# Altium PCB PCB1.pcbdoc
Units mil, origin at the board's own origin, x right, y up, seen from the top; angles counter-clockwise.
Board outline 4456.4 x 1879 mil, 2 copper layers (Top Layer, Bottom Layer), stack 62.2 mil thick; 77 components, 60 nets, 283 pads, 100 vias.
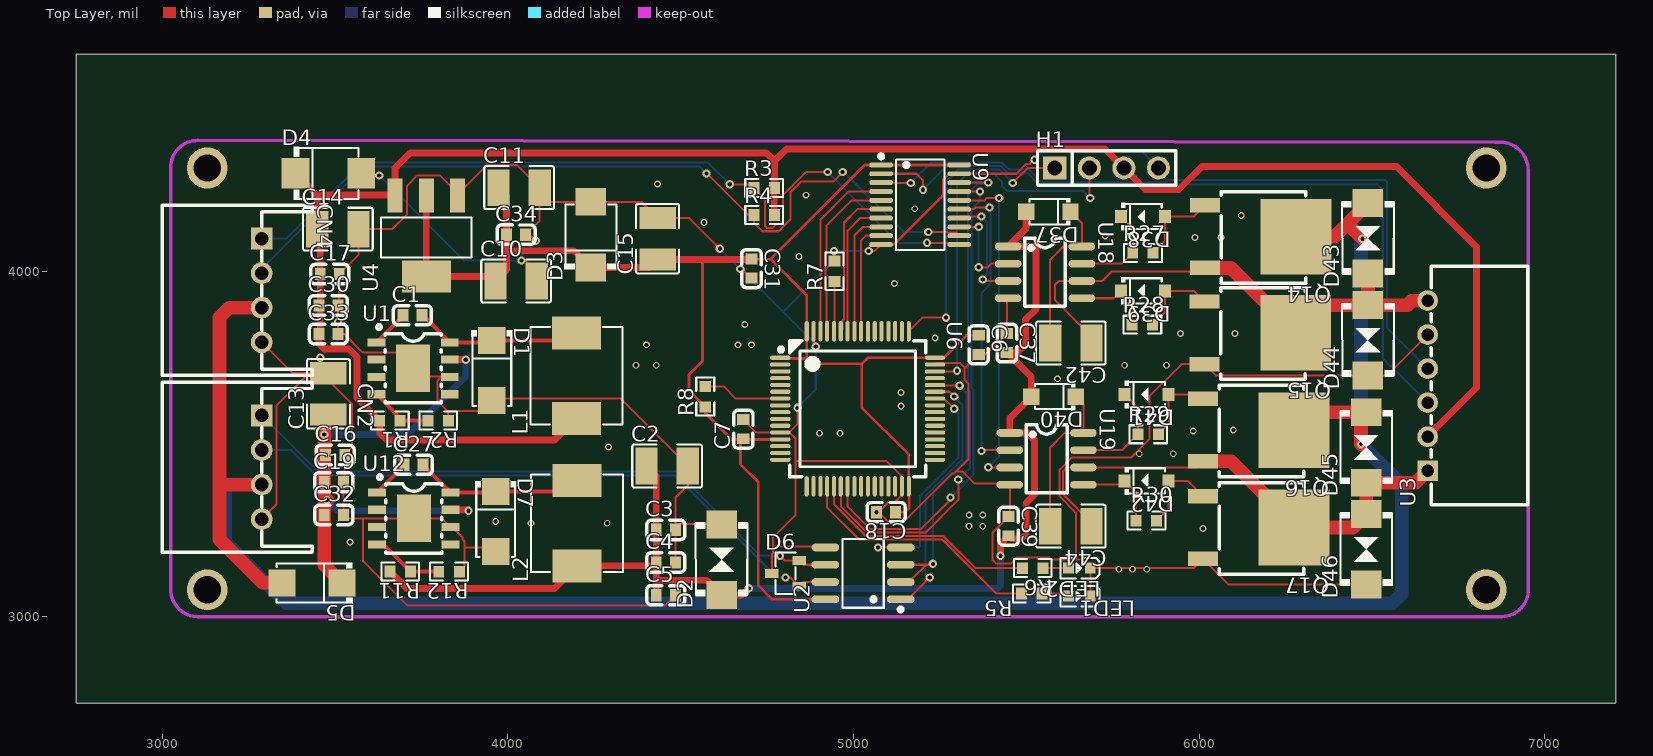
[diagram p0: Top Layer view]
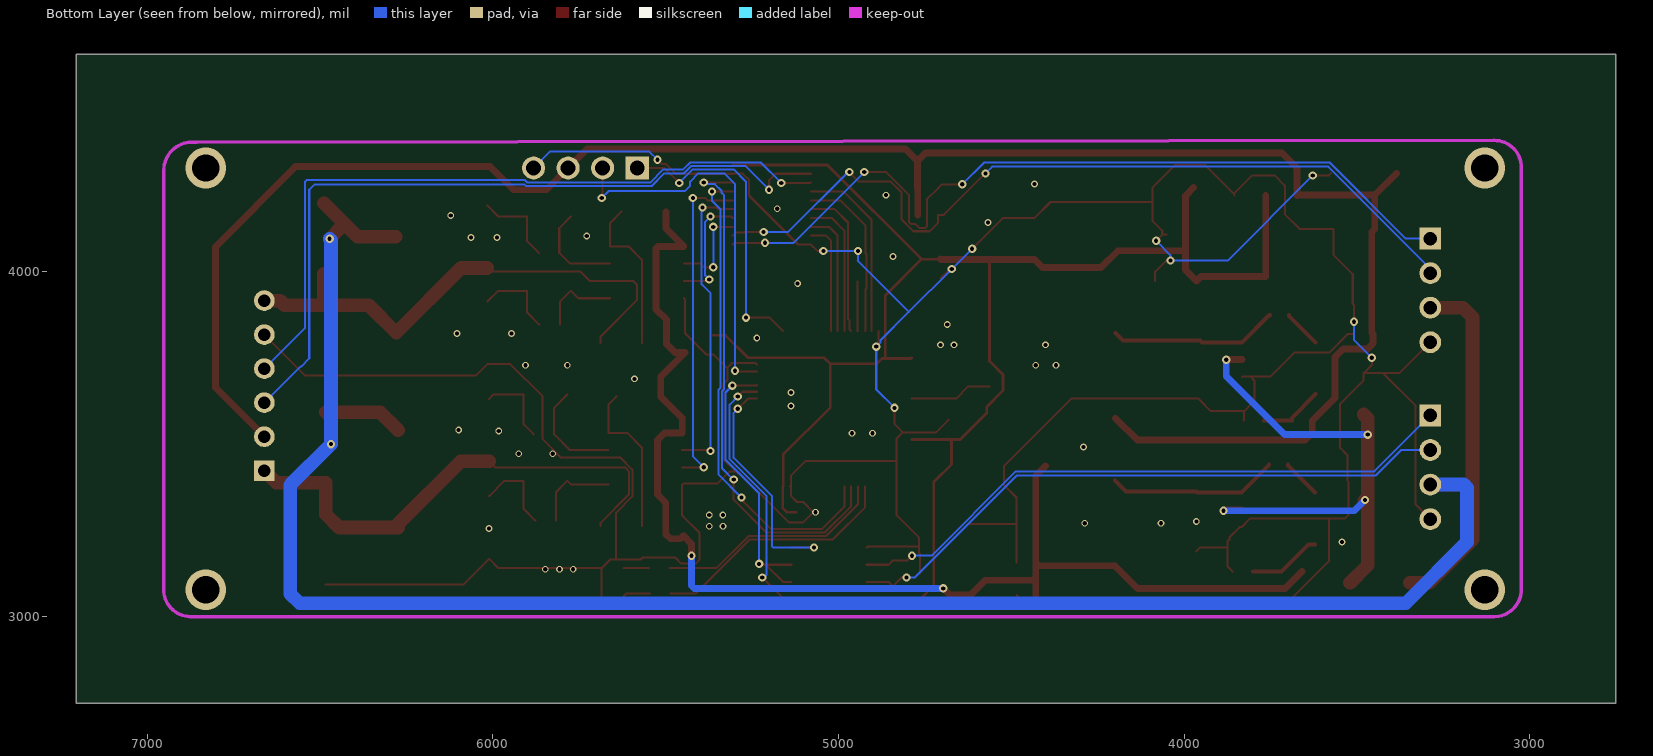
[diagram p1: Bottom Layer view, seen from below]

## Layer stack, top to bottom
Top Solder Mask Layer: solder mask 0.4, Dk 3.3
Top Layer: signal copper 1.4
Dielectric1: surface 59.4, FR4, Dk 4.5
Bottom Layer: signal copper 1.4
Bottom Solder Mask Layer: solder mask 0.4, Dk 3.3

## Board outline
7206.4,2750 2750,2750 2750,4629 7206.4,4629

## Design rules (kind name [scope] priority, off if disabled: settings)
BoardOutlineClearance copperThickness1oz [All] p0: genericclearance=10 ignorepadtopadclearanceinfootprint=FALSE except(0: Arc-SplitContinuation Track-SplitContinuation SMDPad-SplitContinuation THPad-SplitContinuation Via-SplitContinuation Fill-SplitContinuation Poly-SplitContinuation Region-SplitContinuation Text-SplitContinuation)
BoardOutlineClearance copperThickness2oz [All] p0: genericclearance=10 ignorepadtopadclearanceinfootprint=FALSE except(0: Arc-SplitContinuation Track-SplitContinuation SMDPad-SplitContinuation THPad-SplitContinuation Via-SplitContinuation Fill-SplitContinuation Poly-SplitContinuation Region-SplitContinuation Text-SplitContinuation)
BoardOutlineClearance otherClearance [All] p0: genericclearance=10 ignorepadtopadclearanceinfootprint=FALSE except(0: Arc-SplitContinuation Track-SplitContinuation SMDPad-SplitContinuation THPad-SplitContinuation Via-SplitContinuation Fill-SplitContinuation Poly-SplitContinuation Region-SplitContinuation Text-SplitContinuation)
Clearance copperThickness1oz [All] p1: gap=7 ignorepadtopadclearanceinfootprint=FALSE
Clearance copperThickness2oz [All] p1: gap=7 ignorepadtopadclearanceinfootprint=FALSE
Clearance otherClearance [All] p1: gap=7 ignorepadtopadclearanceinfootprint=FALSE
DiffPairsRouting differentialPair [All] p1: maxuncoupledlength=10 minlimit=6 maxlimit=Infinity mostfreqgap=6 toplayer_minwidth=5 toplayer_prefwidth=10 toplayer_maxwidth=100 bottomlayer_minwidth=5 bottomlayer_prefwidth=10 bottomlayer_maxwidth=100
PasteMaskExpansion pasteMaskExpansion [All] p1: expansion=0
PlaneConnect innerPlane [All] p1: planeconnectstyle=Direct reliefexpansion=20 reliefentries=4 reliefconductorwidth=10 reliefairgap=10
PolygonConnect copperRegion [All] p1: connectstyle=Direct reliefentries=4 reliefconductorwidth=10 polygonreliefangle="90 Angle" airgapwidth=10
RoutingVias viaSize [All] p1: viastyle="Through Hole" holewidth=12.0078 minholewidth=11.811 maxholewidth=248.0314 width=12.0078 minwidth=11.811 maxwidth=248.0314
SolderMaskExpansion solderMaskExpansion [IsVia] p1: useseparateexpansions=TRUE expansion=-1000 expansionbottom=-1000
SolderMaskExpansion solderMaskExpansion [All] p2: useseparateexpansions=TRUE expansion=2 expansionbottom=2
Width copperThickness1oz [All] p1: maxlimit=100 minlimit=5 preferedwidth=6
Width copperThickness2oz [All] p1: maxlimit=100 minlimit=8 preferedwidth=10
Width l24V [All] p1: maxlimit=100 minlimit=4 preferedwidth=39
Width i5V [All] p1: maxlimit=100 minlimit=5 preferedwidth=20
Width i3V [All] p1: maxlimit=100 minlimit=5 preferedwidth=8

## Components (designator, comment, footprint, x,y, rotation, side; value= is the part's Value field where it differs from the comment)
C1 "100nF" C0603#1 3723.3,3873 r0 top
C2 "10uF" C1210#1 4460.6,3437 r0 top
C3 "100nF" C0603#2 4456.7,3252 r0 top
C4 "100nF" C0603#2 4456.7,3157.5 r0 top
C5 "100nF" C0603#2 4456.7,3063 r0 top
C6 "100nF" C0603#2 5362.2,3787.4 r270 top
C7 "100nF" C0603#2 4681.1,3543.3 r90 top
C10 "10uF" C1210#1 4023.6,3972.4 r0 top
C11 "10uF" C1210#2 4032.2,4242.3 r0 top
C13 "10uF" C1210#3 3480.3,3645.7 r90 top
C14 "10uF" C1210#3 3507.9,4122 r0 top
C15 "10uF" C1210#3 4433.1,4094.5 r90 top
C16 "100nF" C0603#2 3500,3468.5 r0 top
C17 "100nF" C0603#3 3484.3,3992.1 r0 top
C18 "100nF" C0603#1 5094.5,3303.1 r180 top
C19 "100nF" C0603#3 3496.1,3389.8 r0 top
C27 "100nF" C0603#3 3726.7,3440.3 r0 top
C30 "100nF" C0603#1 3480.3,3901.6 r0 top
C31 "100nF" C0603#1 4704.7,4007.9 r270 top
C32 "100nF" C0603#3 3496.1,3295.3 r0 top
C33 "100nF" C0603#1 3480.3,3818.9 r0 top
C34 "100nF" C0603#1 4023.6,4106.3 r0 top
C37 "100nF" C0603#3 5443.7,3792.6 r270 top
C39 "100nF" C0603#3 5448.7,3262.6 r270 top
C42 "10uF" C1210#3 5628.7,3792.6 r180 top
C44 "10uF" C1210#3 5628.7,3262.6 r180 top
CN2 "2.54-4P WZ-D" CONN-TH_2.54-4P-WZ-D 3287.4,3433.1 r270 top
CN4 "2.54-4P WZ-D" CONN-TH_2.54-4P-WZ-D 3287.4,3944.9 r270 top
D1 "B340A-E3/61T" SMA_L4.3-W2.6-LS5.2-RD 3953.3,3713 r270 top
D2 "SMBJ36CA" SMB_L4.6-W3.6-LS5.4-BI#1 4618.1,3165.4 r90 top
D3 "SMBJ5.0A" SMB_L4.6-W3.6-LS5.4-RD 4240.2,4106.3 r90 top
D4 "SMBJ5.0A" SMB_L4.6-W3.6-LS5.4-RD 3480.3,4283.5 r0 top
D5 "B340A-E3/61T" SMA_L4.3-W2.6-LS5.2-RD 3433.1,3098.4 r180 top
D6 "SM712" SOT-23-3_L2.9-W1.3-P1.90-LS2.4-BR 4803.1,3126 r0 top
D7 "B340A-E3/61T" SMA_L4.3-W2.6-LS5.2-RD 3964.4,3276.1 r270 top
D37 "FR107W" SOD-123FL_L2.7-W1.8-LS3.8-RD 5563.7,4172.6 r180 top
D38 "1N4148W" SOD-123_L2.7-W1.6-LS3.7-FD 5837.7,4158.7 r180 top
D39 "1N4148W" SOD-123_L2.7-W1.6-LS3.7-FD 5837.7,3943.7 r180 top
D40 "FR107W" SOD-123FL_L2.7-W1.8-LS3.8-RD 5578.7,3637.6 r180 top
D41 "1N4148W" SOD-123_L2.7-W1.6-LS3.7-FD 5847.7,3643.7 r180 top
D42 "1N4148W" SOD-123_L2.7-W1.6-LS3.7-FD 5847.7,3393.7 r180 top
D43 "SMBJ36CA" SMB_L4.6-W3.6-LS5.4-BI#2 6488.7,4095.4 r90 top
D44 "SMBJ36CA" SMB_L4.6-W3.6-LS5.4-BI#2 6488.7,3800.4 r90 top
D45 "SMBJ36CA" SMB_L4.6-W3.6-LS5.4-BI#2 6483.7,3490.4 r90 top
D46 "SMBJ36CA" SMB_L4.6-W3.6-LS5.4-BI#2 6483.7,3195.4 r90 top
H1 "PZ254V-11-04P" HDR-TH_4P-P2.54-V-M 5732.3,4299.2 r0 top
L1 "22uH" IND-SMD_L7.0-W6.6_FXL0630#1 4198.3,3698 r90 top
L2 "22uH" IND-SMD_L7.0-W6.6_FXL0630#2 4199.4,3271.1 r90 top
LED1 "" LED_0603 5651.6,3060 r180 top
LED2 "" LED_0603 5651.6,3141.1 r180 top
Q14 "CMD100N08A" TO-252-3_L6.5-W5.8-P4.58-LS9.5-BR#1 6148.7,4100.4 r180 top
Q15 "CMD100N08A" TO-252-3_L6.5-W5.8-P4.58-LS9.5-BR#1 6147.7,3822.3 r180 top
Q16 "CMD100N08A" TO-252-3_L6.5-W5.8-P4.58-LS9.5-BR#2 6142.7,3540.6 r180 top
Q17 "CMD100N08A" TO-252-3_L6.5-W5.8-P4.58-LS9.5-BR#2 6142.7,3258.8 r180 top
R1 "10K" R0603#1 3658.3,3568 r180 top
R2 "10K" R0603#1 3798.3,3568 r180 top
R3 "10K" R0603#1 4741.2,4241.1 r0 top
R4 "10K" R0603#1 4741.2,4163.4 r0 top
R5 "10K" R0603#2 5516,3067.9 r180 top
R6 "10K" R0603#1 5518.7,3141.1 r180 top
R7 "10kΩ" R0603#3 4944.9,4000 r90 top
R8 "10kΩ" R0603#3 4570.9,3637.8 r90 top
R11 "10K" R0603#2 3688.4,3131.4 r180 top
R12 "10K" R0603#3 3829.4,3131.1 r180 top
R27 "10K" R0603#1 5837.7,4053.7 r0 top
R28 "10K" R0603#2 5835.9,3845.6 r0 top
R29 "10K" R0603#1 5852.7,3528.7 r0 top
R30 "10K" R0603#1 5847.7,3278.7 r0 top
U1 "TPS5430DDAR" ESOP-8_L4.9-W3.9-P1.27-LS6.0-TL-EP 3725.6,3719.6 r0 top
U2 "SP3485EEN(UMW)" SOP-8_L5.0-W4.0-P1.27-LS6.0-BL 5027.6,3126 r90 top
U3 "WAFER-XH254WZ-6A" CONN-TH_6P-P2.50_WAFER-XH254WZ-6A 6661.4,3669.3 r90 top
U4 "AMS1117-3.3" SOT-223-3_L6.5-W3.4-P2.30-LS7.0-BR 3763.8,4102.4 r90 top
U6 "STM32F103RCT6" LQFP-64_L10.0-W10.0-P0.50-LS12.0-BL 5011.8,3602.4 r270 top
U9 "74HC245PW,118" TSSOP-20_L6.5-W4.4-P0.65-LS6.4-BL 5192.9,4192.9 r270 top
U12 "TPS5430DDAR" ESOP-8_L4.9-W3.9-P1.27-LS6.0-TL-EP 3727.5,3285.1 r0 top
U18 "EG2104S" SOIC-8_L5.0-W4.0-P1.27-LS6.0-BL 5554.1,3997.2 r270 top
U19 "EG2104S" SOIC-8_L5.0-W4.0-P1.27-LS6.0-BL 5558.7,3457.6 r270 top

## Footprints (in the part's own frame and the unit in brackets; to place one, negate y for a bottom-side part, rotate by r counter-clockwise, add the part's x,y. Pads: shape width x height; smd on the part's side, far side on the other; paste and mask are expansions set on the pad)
C0603#1 [mil]
  rect 31.5x35.4 smd: 1(-27.5,0) 2(27.6,0)
  silkscreen extent -55,-28 55,28
C0603#2 [mil]
  rect 31.5x35.4 smd: 1(-27.6,0) 2(27.6,0)
  silkscreen extent -55,-28 55,28
C0603#3 [mil]
  rect 31.5x35.4 smd: 1(-27.6,0) 2(27.5,0)
  silkscreen extent -55,-28 55,28
C1210#1 [mil]
  rect 64.4x106.3 smd paste-3937 mask+2: 1(-59.7,0) 2(59.8,0)
  silkscreen extent -101,-62 101,62
C1210#2 [mil]
  rect 64.4x106.3 smd paste-3937 mask+2: 1(-59.7,0) 2(59.7,0)
  silkscreen extent -101,-62 101,62
C1210#3 [mil]
  rect 64.4x106.3 smd paste-3937 mask+2: 1(-59.8,0) 2(59.7,0)
  silkscreen extent -101,-62 101,62
CONN-TH_2.54-4P-WZ-D [mil]
  rect 63x63 hole 39.4 paste+0 mask+2: 1(-150,0)
  round 63 hole 39.4 paste+0 mask+2: 2(-50,0) 3(50,0) 4(150,0)
  silkscreen extent -246,-287 246,146
CONN-TH_6P-P2.50_WAFER-XH254WZ-6A [mil]
  rect 60x60 hole 36: 1(-246.1,0)
  round 60 hole 36: 2(-147.6,0) 3(-49.2,0) 4(49.2,0) 5(147.6,0) 6(246.1,0)
  silkscreen extent -345,-290 345,-10
ESOP-8_L4.9-W3.9-P1.27-LS6.0-TL-EP [mm]
  rect 1.3x0.599 smd: 1(-2.7,1.905) 2(-2.7,0.635) 3(-2.7,-0.635) 4(-2.7,-1.905) 5(2.7,-1.905) 6(2.7,-0.635) 7(2.7,0.635) 8(2.7,1.905)
  rect 2.499x3.5 smd: 9(0,0)
  silkscreen extent -2.67,-2.55 2.05,3.2
HDR-TH_4P-P2.54-V-M [mil]
  rect 66.9x66.9 hole 43.3: 1(-150,0)
  round 66.9 hole 43.3: 2(-50,0) 3(50,0) 4(150,0)
  silkscreen extent -200,-50 200,50
IND-SMD_L7.0-W6.6_FXL0630#1 [mil]
  rect 95.4x142.5 smd: 1(123.1,0) 2(-123.2,0)
  silkscreen extent -141,-133 141,133
IND-SMD_L7.0-W6.6_FXL0630#2 [mil]
  rect 95.4x142.5 smd: 1(123.2,0) 2(-123.1,0)
  silkscreen extent -141,-133 141,133
LED_0603 [mil]
  rect 31.5x31.5 smd paste+0 mask+2: 1(-33.5,-0.4) 2(29.5,-0.2)
  silkscreen extent -61,-30 53,30
LQFP-64_L10.0-W10.0-P0.50-LS12.0-BL [mil]
  oval 11.8x59.1 smd: 1(-147.6,-223.9) 2(-127.9,-223.9) 3(-108.2,-223.9) 4(-88.5,-223.9) 5(-68.9,-223.9) 6(-49.2,-223.9) 7(-29.5,-223.9) 8(-9.8,-223.9) 9(9.9,-223.9) 10(29.6,-223.9) 11(49.2,-223.9) 12(68.9,-223.9) 13(88.6,-223.9) 14(108.3,-223.9) 15(128,-223.9) 16(147.7,-223.9) 33(147.7,224) 34(128,224) 35(108.3,224) 36(88.6,224) 37(68.9,224) 38(49.2,224) 39(29.6,224) 40(9.9,224) 41(-9.8,224) 42(-29.5,224) 43(-49.2,224) 44(-68.9,224) 45(-88.5,224) 46(-108.2,224) 47(-127.9,224) 48(-147.6,224)
  oval 59.1x11.8 smd: 17(224.4,-147.2) 18(224.4,-127.5) 19(224.4,-107.8) 20(224.4,-88.1) 21(224.4,-68.4) 22(224.4,-48.7) 23(224.4,-29.1) 24(224.4,-9.4) 25(224.4,10.3) 26(224.4,30) 27(224.4,49.7) 28(224.4,69.4) 29(224.4,89.1) 30(224.4,108.7) 31(224.4,128.4) 32(224.4,148.1) 49(-224.4,148.1) 50(-224.4,128.4) 51(-224.4,108.7) 52(-224.4,89.1) 53(-224.4,69.4) 54(-224.4,49.7) 55(-224.4,30) 56(-224.4,10.3) 57(-224.4,-9.4) 58(-224.4,-29.1) 59(-224.4,-48.7) 60(-224.4,-68.4) 61(-224.4,-88.1) 62(-224.4,-107.8) 63(-224.4,-127.5) 64(-224.4,-147.2)
  silkscreen extent -197,-228 197,197
R0603#1 [mil]
  rect 31.8x34 smd paste-3937 mask+2: 1(-29.7,0) 2(29.6,0)
  silkscreen extent -55,-26 54,26
R0603#2 [mil]
  rect 31.8x34 smd paste-3937 mask+2: 1(-29.6,0) 2(29.7,0)
  silkscreen extent -54,-26 55,26
R0603#3 [mil]
  rect 31.8x34 smd paste-3937 mask+2: 1(-29.7,0) 2(29.7,0)
  silkscreen extent -54,-26 54,26
SMA_L4.3-W2.6-LS5.2-RD [mil]
  rect 78.7x78.7 smd: 1(-86.6,0) 2(86.6,0)
  silkscreen extent -117,-59 102,59
SMB_L4.6-W3.6-LS5.4-BI#1 [mil]
  rect 80.6x88.2 smd: 1(-102.1,0) 2(102,0)
  silkscreen extent -105,-75 108,75
SMB_L4.6-W3.6-LS5.4-BI#2 [mil]
  rect 80.6x88.2 smd: 1(-102,0) 2(102,0)
  silkscreen extent -105,-75 108,75
SMB_L4.6-W3.6-LS5.4-RD [mil]
  rect 80.6x88.2 smd: 1(-95,0) 2(95,0)
  silkscreen extent -100,-77 88,77
SOD-123_L2.7-W1.6-LS3.7-FD [mil]
  rect 34.6x37.8 smd: 1(-63.4,0) 2(63.4,0)
  silkscreen extent -54,-39 63,40
SOD-123FL_L2.7-W1.8-LS3.8-RD [mil]
  rect 47.2x47.2 smd: 1(-64.4,0) 2(64.3,0)
  silkscreen extent -63,-40 54,39
SOIC-8_L5.0-W4.0-P1.27-LS6.0-BL [mil]
  oval 22.4x76.8 smd: 1(-75,-106.5) 2(-25,-106.5) 3(25,-106.5) 4(75,-106.5) 5(75,106.5) 6(25,106.5) 7(-25,106.5) 8(-75,106.5)
  silkscreen extent -99,-59 98,59
SOP-8_L5.0-W4.0-P1.27-LS6.0-BL [mil]
  oval 22.6x80.1 smd: 1(-75,-108.9) 2(-25,-108.9) 3(25,-108.9) 4(75,-108.9) 5(75,109) 6(25,109) 7(-25,109) 8(-75,109)
  silkscreen extent -110,-115 99,60
SOT-23-3_L2.9-W1.3-P1.90-LS2.4-BR [mil]
  rect 39.4x25.6 smd: 1(39.4,-37.4) 2(39.4,37.4) 3(-39.3,0)
  silkscreen extent -28,-60 29,60
SOT-223-3_L6.5-W3.4-P2.30-LS7.0-BR [mil]
  rect 98.4x43.3 smd: 1(116.9,-90.5) 2(116.9,0) 3(116.9,90.6)
  rect 92.1x141.7 smd: 4(-117,0)
  silkscreen extent -62,-131 54,131
TO-252-3_L6.5-W5.8-P4.58-LS9.5-BR#1 [mil]
  rect 87.3x41.9 smd: 1(131.8,-90.5) 3(131.8,90.6)
  rect 204.9x218.6 smd: 2(-131.9,0)
  silkscreen extent -160,-130 85,135
TO-252-3_L6.5-W5.8-P4.58-LS9.5-BR#2 [mil]
  rect 87.3x41.9 smd: 1(131.8,-90.6) 3(131.8,90.5)
  rect 204.9x218.6 smd: 2(-131.9,0)
  silkscreen extent -160,-130 85,135
TSSOP-20_L6.5-W4.4-P0.65-LS6.4-BL [mil]
  oval 14.3x68.6 smd: 1(-115.2,-113) 2(-89.6,-113) 3(-64,-113) 4(-38.4,-113) 5(-12.8,-113) 6(12.8,-113) 7(38.4,-113) 8(64,-113) 9(89.6,-113) 10(115.1,-113) 11(115.1,113) 12(89.6,113) 13(64,113) 14(38.4,113) 15(12.8,113) 16(-12.8,113) 17(-38.4,113) 18(-64,113) 19(-89.6,113) 20(-115.2,113)
  silkscreen extent -146,-119 131,70

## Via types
v1: diameter 24, hole 12, Top Layer to Bottom Layer, 52 vias
v2: diameter 19.7, hole 12, Top Layer to Bottom Layer, 44 vias
v3: diameter 118.1, hole 78.7, Top Layer to Bottom Layer, 4 vias

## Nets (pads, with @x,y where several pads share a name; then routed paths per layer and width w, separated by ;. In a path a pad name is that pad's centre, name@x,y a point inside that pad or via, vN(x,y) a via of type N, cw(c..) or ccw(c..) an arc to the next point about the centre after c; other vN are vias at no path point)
3.3V: C6.1 C7.1 C10.1 C11.1 C15.1 C18.1 C31.1 C34.1 D3.1 R8.1 U2.8 U4.2 U4.4 U6.1 U6.13 U6.32 U6.48 U6.64 U9.1 U9.20 | length 5040.3
  Top Layer w7.9: 4564,4034.7 4563,4033.8 4563,3740.2 4523.6,3700.8 4523.6,3655.4 R8.1 4570.9,3590.6 4647.6,3513.8 C7.1@4679.1,3513.8 ; C7.1 C7.1@4679.1,3513.8 ; C31.1 4759.8,4035.4 ; U6.13 C7.1@4679.1,3513.8 ; U6.1 4789.8,3748 4865.1,3748 ; U2.8 4764,3051 4724.4,3090.6 4724.4,3389.8 4673.2,3440.9 4673.2,3507.9 C7.1@4679.1,3513.8 ; C18.1 5149.6,3303.1 5161.4,3315 5161.4,3376.5 U6.32 5159.9,3470 5023.6,3606.3 5023.6,3732.3 ; U9.20 U9.1 5032.5,4308.1 4759.8,4035.4 ; C6.1 5326.8,3815 5261.8,3750 U6.48 5041.3,3750 5023.6,3732.3 ; 4759.8,4035.4 4864.6,3930.6 U6.64 4864.6,3748.5 4865.1,3748 ; 4865.1,3748 4874,3748 4889.8,3732.3 5023.6,3732.3
  Top Layer w19.7: U4.2 U4.4 3950.9,3985.4 C10.1 3996.1,4004.6 3996.1,4059.7 ; C11.1 3996.1,4218.7 C34.1 3996.1,4059.7 ; C31.1 4704,4034.7 4564,4034.7 C15.1 4409.6,4011.3 D3.1 4191.7,4059.7 3996.1,4059.7
12V: C2.1 C3.1 C4.1 C5.1 C37.2 C39.2 D2.1 D37.2 D40.2 L2.2 R11.2 U18.1 U19.1 | length 3658.2
  Top Layer w19.7: R11.2 3707.5,3082.7 4134.1,3082.7 L2.2 4419.6,3148 C4.1 ; C2.1 4429.1,3408.8 C3.1 C4.1 ; C5.1 4429.1,3115 ; v1(4696.8,3082.7) 4677.5,3063.3 D2.1 4575.1,3106.3 4437.8,3106.3 4429.1,3115 ; v1(5425.2,3177.2) 5425.2,3211.5 C39.2 5457.6,3226.2 5486.1,3226.2 5500,3240.2 5500,3330.7 5523.6,3354.3 5523.6,3511.8 5502.8,3532.6 U19.1 5452.2,3575.5 D40.2 5514.4,3694.4 C37.2 5473.7,3765.1 5498,3789.4 5498,3860.2 5527.6,3889.8 5527.6,4066.9 5522.2,4072.2 U18.1 5499.4,4124 D37.2 ; 4429.1,3115 C4.1
  Bottom Layer w19.7: v1(4696.8,3082.7) 5417.3,3082.7 5425.2,3090.6 v1(5425.2,3177.2)
24V: C13.1 C16.1 C19.1 C32.1 D5.1 U1.7 U12.7 | length 1565.5
  Top Layer w19.7: U1.7 3877.5,3744.6 v1(3878,3744.1) ; U12.7 3882.8,3310.1 v1(3885.8,3307.1)
  Top Layer w39.4: v1(3476.4,3338.6) v1@3478.5,3336.4 ; C13.1 3468.5,3574.1 v1(3468.5,3527.6) C19.1 C32.1 3468.5,3149.6 D5.1
  Bottom Layer w19.7: v1(3468.5,3527.6) 3708.7,3527.6 3878,3696.9 v1(3878,3744.1) ; v1(3476.4,3338.6) 3507.9,3307.1 v1(3885.8,3307.1)
24V-P: CN2.3 CN4.3 D5.2 D43.2 D45.2 Q14.2 Q16.2 | length 6611.7
  Top Layer w39.4: CN2.3 3287.2,3382.9 3165.1,3382.9 ; CN4.3 3192.9,3894.9 3165.1,3867 3165.1,3382.9 ; D5.2 3291.1,3098.4 3165.1,3224.4 3165.1,3382.9 ; Q16.2 6326.4,3592.4 D45.2 6468.5,3577.2 v1(6468.5,3500) ; Q14.2 6391.7,4100.4 6436.5,4145.2 ; v1(6472.4,4094.5) 6436.5,4130.4 6436.5,4145.2 ; D43.2 6436.5,4145.2
  Bottom Layer w39.4: CN2.3 3190.2,3383.1 3181.1,3374 3181.1,3216.5 3358.3,3039.4 6559.1,3039.4 6586.9,3067.2 6586.9,3381.6 v1(6468.5,3500) 6468.5,4090.6 v1(6472.4,4094.5)
$1N1: C1.1 U1.1 | length 110.1
  Top Layer w11.8: U1.1 3695.8,3871.1 C1.1
$1N2: C27.1 U12.1 | length 112.5
  Top Layer w11.8: U12.1 3699.1,3438 C27.1
$1N3: C1.2 D1.1 L1.1 U1.8 | length 490.9
  Top Layer w11.8: C1.2 3753.5,3873 U1.8 3948.3,3794.6 D1.1 4176.8,3799.6 L1.1
$1N4: C27.2 D7.1 L2.1 U12.8 | length 493
  Top Layer w11.8: C27.2 3833.8,3360.7 U12.8 3961.8,3360.1 D7.1 4167.9,3362.7 L2.1
$1N7: R1.1 R2.2 U1.4 | length 185.8
  Top Layer w11.8: U1.4 3688,3575.9 R1.1 R2.2
$1N8: R11.1 R12.2 U12.4 | length 211.3
  Top Layer w11.8: U12.4 3639.4,3210.1 R11.1 3799.4,3131.4 R12.2
$1N71: U6.57 U9.8 | length 365
  Top Layer w5.9: U6.57 5002.4,4103.9 5027.4,4128.9 U9.8
$1N72: U6.58 U9.7 | length 403.5
  Top Layer w5.9: U6.58 4982.7,4118 5019.3,4154.5 U9.7
$1N73: U6.59 U9.6 | length 442
  Top Layer w5.9: U6.59 4967.9,3831.6 4967.9,3856.5 4972.4,3861.1 4972.4,4141.4 5011.1,4180.1 U9.6
$1N74: U6.61 U9.5 | length 497.4
  Top Layer w5.9: U6.61 4921.3,3829.2 4921.3,3948.4 4918.9,3950.8 4918.9,4049.2 4921.3,4051.6 4921.3,4132.1 4994.8,4205.7 U9.5
$1N75: U6.62 U9.4 | length 532
  Top Layer w5.9: U6.62 4904,4148.6 4986.7,4231.3 U9.4
$1N90: C44.2 D40.1 U19.8 | length 455.5
  Top Layer w5.9: C44.2 5569,3490.3 5611.4,3532.6 U19.8 5665.2,3615.5 D40.1
$1N92: H1.1 U6.49 | length 881.4
  Top Layer w5.9: U6.49 5199.3,3866.1 v1(5267.7,3866.1) ; v1(5460.6,4255.9) 5503.9,4299.2 H1.1
  Bottom Layer w5.9: v1(5267.7,3866.1) 5267.7,4259.8 5303.1,4295.3 5421.3,4295.3 v1(5460.6,4255.9)
$1N93: H1.2 U6.46 | length 1126.5
  Top Layer w5.9: U6.46 5297.2,3710.6 v1(5299.2,3712.6) ; H1.2 5682.3,4215.4 v1(5685,4212.6)
  Bottom Layer w5.9: v1(5299.2,3712.6) 5299.2,4252 5330.7,4283.5 5405.5,4283.5 5429.1,4259.8 5429.1,4248 5444.9,4232.3 5665.4,4232.3 v1(5685,4212.6)
$1N120: D38.1 Q14.1 R27.2 | length 248.2
  Top Layer w5.9: R27.2 5901.1,4087.4 D38.1 5984.7,4158.7 Q14.1
$1N121: D41.1 Q16.1 R29.2 | length 231.9
  Top Layer w5.9: R29.2 5911.1,3557.4 D41.1 5998.4,3643.7 Q16.1
$1N122: D42.1 Q17.1 R30.2 | length 247.2
  Top Layer w5.9: R30.2 5911.1,3312.4 D42.1 5966.6,3393.7 Q17.1
$1N123: D39.1 Q15.1 R28.2 | length 240.4
  Top Layer w5.9: R28.2 5901.1,3881.1 D39.1 5985.1,3943.7 Q15.1
$1N124: D38.2 R27.1 U18.7 | length 279.4
  Top Layer w5.9: U18.7 5776.6,4022.2 R27.1 5808,4125 D38.2
$1N125: D39.2 R28.1 U18.5 | length 234
  Top Layer w5.9: U18.5 5752.8,3922.2 D39.2 5806.3,3911.7 R28.1
$1N126: D41.2 R29.1 U19.7 | length 308
  Top Layer w5.9: U19.7 5777,3482.6 R29.1 5823,3605 D41.2
$1N127: D42.2 R30.1 U19.5 | length 252.7
  Top Layer w5.9: U19.5 5773.2,3382.6 D42.2 5818,3360 R30.1
$1N128: C42.2 D37.1 U18.8 | length 462.4
  Top Layer w5.9: C42.2 5569,4033.6 5607.7,4072.2 U18.8 5660.6,4140.1 D37.1
$1N138: R8.2 U6.7 | length 239.5
  Top Layer w5.9: R8.2@4563,3667.2 4624.1,3667.2 4659.4,3631.9 U6.7
$1N139: R7.1 U6.60 | length 144.1
  Top Layer w5.9: U6.60 4944.9,3828.3 R7.1
$1N154: U6.30
$1N155: U6.29
$1N156: U6.28
$1N157: U6.27
$1N158: U6.26
$1N159: R6.2 U6.21 | length 674.3
  Top Layer w5.9: U6.21 4943.4,3326.1 5035.1,3234.3 5260,3234.3 5353.2,3141.1 R6.2
$1N160: R5.2 U6.20 | length 727.1
  Top Layer w5.9: U6.20 4923.7,3316.5 5015.7,3224.4 5255.9,3224.4 5412.5,3067.9 R5.2
$1N221: U6.56 U9.9 | length 326.4
  Top Layer w5.9: U6.56 5022.1,4089.9 5035.6,4103.3 U9.9
$1N223: LED1.2 R5.1 | length 79.7
  Top Layer w5.9: R5.1 5614.4,3067.9 LED1.2
$1N227: LED2.2 R6.1 | length 73.8
  Top Layer w5.9: R6.1 5621.9,3141.1 LED2.2
+5V: C14.1 C17.1 C30.1 C33.1 D4.1 H1.3 L1.2 R1.2 R3.2 R4.2 U3.2 U4.3 | length 5914.8
  Top Layer w19.7: D4.1 3448.1,4220.6 ; L1.2 4135.3,3511.8 3649.6,3511.8 3628.7,3532.7 R1.2 3563,3633.7 3563,3752 3539.4,3775.6 3468.5,3775.6 3452.8,3791.3 C33.1 3456.7,3822.8 C17.1 3456.7,4113.5 C14.1 3448.1,4220.6 ; R4.2 R3.2 4771.7,4242 4771.7,4318.9 ; U3.2 6803.1,3663.4 6803.1,4070.9 6570.9,4303.1 6007.9,4303.1 5940.9,4236.2 5845.3,4236.2 H1.3 5727.6,4353.9 4806.6,4353.9 4771.7,4318.9 ; 3448.1,4220.6 3671.9,4220.6 U4.3 3673.2,4299.2 3716.5,4342.5 4748,4342.5 4771.7,4318.9
A: U6.22 U9.18 | length 1527.5
  Top Layer w5.9: U6.22 4963.1,3320.4 5039.2,3244.3 5208.8,3244.3 5303.1,3338.6 5303.1,3395.9 v1@5304,3396.8 ; U9.18 v1(5389.8,4256.9)
  Bottom Layer w5.9: v1@5304,3396.8 5336.7,3429.5 5336.7,3653.7 5330.7,3659.7 5330.7,4220.5 5338.6,4228.3 5338.6,4233.4 5357.5,4252.2 5385.1,4252.2 v1(5389.8,4256.9)
  other v1: 5303.1,3397.7
A485: CN2.1 D6.2 U2.6 | length 1810.2
  Top Layer w5.9: v1(4787.4,3177.2) 4801.2,3163.4 D6.2 4854.9,3151 U2.6
  Bottom Layer w5.9: CN2.1 3449.2,3421.3 4486.5,3421.3 4730.6,3177.2 v1(4787.4,3177.2)
AO: U3.3 U9.2 | length 2219.4
  Top Layer w5.9: U9.2 5182.1,4282.5 5200.8,4263.8 v1(5200.8,4236.2)
  Bottom Layer w5.9: v1(5200.8,4236.2) 5269.8,4305.2 5425.4,4305.2 5447.1,4283.5 5504.4,4283.5 5541,4246.9 5904,4246.9 5909,4252 6515.7,4252 6531.5,4236.2 6531.5,3748 6555.1,3724.4 6557.1,3724.4 U3.3
B: U6.23 U9.17 | length 1410.4
  Top Layer w5.9: U6.23 4982.4,3377.7 4982.4,3320.7 4992.5,3310.6 4992.5,3310.1 5048.5,3254.2 5195.1,3254.2 5280.5,3339.5 v1(5280.5,3345.5) ; U9.17 v1(5366.1,4231.3)
  Bottom Layer w5.9: v1(5280.5,3345.5) 5346.6,3411.7 5346.6,3657.8 5341.3,3663.2 5341.3,4179.8 5366.1,4204.7 v1(5366.1,4231.3)
B485: CN2.2 D6.1 U2.7 | length 1799.8
  Top Layer w5.9: v1(4803.1,3114.2) 4816.9,3114.2 D6.1 4854.9,3101 U2.7
  Bottom Layer w5.9: CN2.2 3371.3,3483.1 3444.9,3409.4 4484.3,3409.4 4779.5,3114.2 v1(4803.1,3114.2)
BO: U3.4 U9.3 | length 2107.4
  Top Layer w5.9: U9.3 5080.9,4255.9 v1(5165.4,4255.9)
  Bottom Layer w5.9: v1(5165.4,4255.9) 5224.6,4315.1 5429.5,4315.1 5449.3,4295.3 5506.7,4295.3 5545.1,4256.8 5899.8,4256.8 5907.1,4264 6539.1,4264 6543.3,4259.8 6543.3,3836.6 U3.4
DE: U2.2 U2.3 U6.44 | length 824.7
  Top Layer w5.9: U2.2 5160,3101 5210,3151 ; U2.3 5210,3151 ; v1(5229.6,3153.5) 5227,3151 5210,3151 ; U6.44 5237.7,3669.3 v1(5307.1,3669.3)
  Bottom Layer w5.9: v1(5229.6,3153.5) 5229.6,3357.3 5326.8,3454.5 5326.8,3649.6 v1(5307.1,3669.3)
GND: C2.2 C3.2 C4.2 C5.2 C6.2 C7.2 C10.2 C11.2 C13.2 C14.2 C15.2 C16.2 C17.2 C18.2 C19.2 C30.2 C31.2 C32.2 C33.2 C34.2 C37.1 C39.1 CN2.4 CN4.4 D1.2 D2.2 D3.2 D4.2 D6.3 D7.2 D44.1 D46.1 H1.4 LED1.1 LED2.1 Q15.3 Q17.3 R2.1 R7.2 R12.1 U1.6 U1.9 U2.5 U3.5 U4.1 U6.12 U6.31 U6.47 U6.63 U9.10 U9.19 U12.6 U12.9 U18.4 U19.4 | length 14872.2
  Top Layer w5.9: CN2.4 3329.7,3325.4 3329.7,3610.9 3424.2,3705.4 ; CN4.4 3376.9,3705.4 3424.2,3705.4 ; v1(3456.7,3750) 3456.7,3729 C13.2 ; D4.2 3581.2,4277.6 v1(3627.7,4277.6) ; R2.1 3826,3570 3826,3595.6 ; U1.6 3830.5,3696 U1.6@3808.3,3696 ; U4.1 U4.1@3855.7,4224.6 ; R12.1 3874.2,3146.2 3874.2,3201.1 ; D7.2 3952.8,3201.1 3874.2,3201.1 ; v1(4039.4,4031.2) 4051.2,4031.2 4083.4,3999 C10.2 ; C34.2 C34.2@4063,4106.3 ; v1(4080.7,4088.6) C34.2@4063,4106.3 ; D3.2 D3.2@4240.2,4200.8 ; C5.2 4454.7,3033.5 3708.7,3033.5 3581,3161.1 3581,3285.1 ; C4.2 C3.2 4484.9,3252.7 C3.2@4484.9,3268.7 ; v1(4613.2,4065.6) 4524.6,4154.2 C15.2 4386.5,4200.8 D3.2@4240.2,4200.8 ; D2.2 4616.8,3268.7 C3.2@4484.9,3268.7 ; v1(4672.2,4006.6) 4678.4,4006.6 C31.2 ; C7.2 4718.5,3533.5 U6.12 4788.6,3534.2 U6.12@4814,3534.2 ; D6.3 4763.8,3182.8 4766.7,3185.7 4766.7,3203.4 ; v1(4837.6,3605) 4837.6,3557.8 U6.12@4814,3534.2 ; U6.63 4884.3,3788.6 v1(4890.7,3782.2) ; U2.5 4916.1,3203.4 4766.7,3203.4 ; v1(4943.3,4059.2) 4943.3,4031.2 R7.2 ; v1(5043.7,4059.2) 5061.3,4059.2 U9.10 5117.1,4077.8 5258.9,4219.5 5258.9,4264.9 5276.6,4282.6 U9.19@5305.8,4282.6 ; v2(5066.9,3303.1) C18.2@5072.8,3303.1 ; U6.31 U6.31@5137.8,3375.5 ; U6.47 5239.7,3734.3 5309.1,3734.3 5320.9,3722.4 ; U9.19 5471.3,4282.5 5499.8,4311 5511.6,4311 v1(5523.5,4322.8) ; U18.4 5443.7,3918.4 C37.1 5383.4,3759.8 C6.2 5324.8,3722.4 5320.9,3722.4 ; LED1.1 LED2.1 ; D46.1 6085.8,3093.4 Q17.3 5984.2,3141.5 LED2.1 ; U3.5 6542.9,3698.4 D44.1 6049.3,3698.4 Q15.3 5949.3,3731.7 5856.2,3638.6 5856.2,3514.6 5803.1,3461.5 5631.8,3461.5 5596.4,3426 5596.4,3349.3 5643.6,3302 5643.6,3166.2 ; 3424.2,3705.4 C13.2 ; C13.2 3480.3,3684.7 3548.2,3616.8 3548.2,3489.2 C16.2 3527.6,3393.7 C19.2 C32.2 3533.8,3285.1 3581,3285.1 ; 3581,3285.1 U12.9 3808.8,3285.1 U12.6 3838.8,3260.1 3868.3,3230.6 3868.3,3224.7 3874.2,3218.8 3874.2,3201.1 ; U1.6@3808.3,3696 3796.5,3684.2 3796.5,3625.1 3826,3595.6 ; U1.6@3808.3,3696 3749.2,3696 U1.9 3679.4,3765.7 3578.7,3765.7 3525.6,3818.9 C33.2 v1(3507.9,3854.3) C30.2 3511.8,3905.5 C17.2 3567.6,4047.9 C14.2 3664.5,4122 3708.1,4165.6 3708.1,4248.2 3737.6,4277.8 3802.6,4277.8 U4.1@3855.7,4224.6 ; 3826,3595.6 3922.5,3595.6 D1.2 3959.2,3632.3 4325.1,3632.3 C2.2 4520.4,3380.9 4484.9,3345.5 C3.2@4484.9,3268.7 ; U4.1@3855.7,4224.6 3938.4,4307.3 4027,4307.3 C11.2 C11.2@4091.9,4200.2 ; C34.2@4063,4106.3 4063,4118.1 4091.9,4147 C11.2@4091.9,4200.2 ; C11.2@4091.9,4200.2 4239.6,4200.2 D3.2@4240.2,4200.8 ; 4766.7,3203.4 4766.7,3229 4831.7,3294 4831.7,3451.5 ; U6.12@4814,3534.2 4831.7,3516.4 4831.7,3451.5 ; 4831.7,3451.5 5094.8,3451.5 5137.8,3408.5 U6.31@5137.8,3375.5 ; C18.2@5072.8,3303.1 5102.4,3332.7 5120.1,3332.7 5137.8,3350.4 U6.31@5137.8,3375.5 ; C18.2@5072.8,3303.1 5102.4,3273.6 5143.7,3273.6 5285.4,3415.4 5291.3,3415.4 5297.2,3421.3 ; 5297.2,3421.3 5315,3421.3 5350.4,3385.8 5449,3385.8 U19.4 5452.2,3293.7 C39.1 5401.5,3243 5401.5,3166.2 5413.3,3154.4 5454.6,3154.4 5472.4,3172.1 5566.8,3172.1 5572.8,3166.2 5643.6,3166.2 ; 5297.2,3421.3 5332.7,3456.7 5332.7,3675.2 5320.9,3687 5320.9,3722.4 ; 5643.6,3166.2 5660.4,3166.2 LED2.1
  Bottom Layer w5.9: v1(3456.7,3750) 3507.9,3801.2 v1(3507.9,3854.3) ; v1(3627.7,4277.6) 3874,4031.2 v1(4039.4,4031.2) 4039.4,4047.2 v1(4080.7,4088.6) ; v1(4613.2,4065.6) v1(4672.2,4006.6) 4796.3,3882.6 ; v1(4837.6,3605) 4890.7,3658.2 v1(4890.7,3782.2) 4878.9,3794 4878.9,3799.9 4796.3,3882.6 ; v1(5043.7,4059.2) v1(4943.3,4059.2) 4943.3,4029.7 4796.3,3882.6 ; v1(5523.5,4322.8) 5547.1,4346.5 5835,4346.5 H1.4
  other v2: 5767.7,3137.8 5807.1,3137.8 5848.5,3137.8 3543.3,3216.5 6010.9,3256.3 5333.7,3262.6 5374,3262.6 4066.5,3271.1 4287.1,3271.1 3964.4,3276.1 5334.6,3295.3 5374,3295.3 5826.8,3472.4 5925.2,3472.4 4291.3,3492.1 4901.6,3531.5 4960.6,3531.5 5983.2,3538.1 6099.1,3540.6 5137.8,3610.2 5137.8,3649.6 5590.6,3689 4370.1,3728.3 4429.1,3728.3 5784.6,3728.3 5905.5,3728.3 4400.9,3787.4 4665.4,3787.4 4704.7,3787.4 5236.2,3807.1 5946.2,3819.8 6104.2,3819.8 4685,3846.5 5118.1,3964.6 4842.5,4043.3 5988.2,4097.9 6063.7,4097.9 5728.3,4102.4 4566.9,4141.7 6122,4161.4 5177.2,4181.1 4862.2,4220.5 4433.1,4253.2
IN1: CN4.2 R4.1 U9.12 | length 2437.5
  Top Layer w5.9: v1(4574.8,4283.5) 4694.8,4163.4 R4.1 4711.5,4140.6 4736,4116.1 4783,4116.1 4817,4150.1 4817,4228.2 4848.7,4259.8 4940.9,4259.8 v1(4968.5,4287.4) ; v1(5216.5,4114.2) 5270.8,4114.2 5272.1,4112.8 5296.5,4112.8 U9.12
  Bottom Layer w5.9: CN4.2 3287.4,4007.9 3582.7,4303.1 4555.1,4303.1 v1(4574.8,4283.5) ; v1(4968.5,4287.4) 4972.4,4287.4 5145.7,4114.2 v1(5216.5,4114.2)
IN2: CN4.1 R3.1 U9.11 | length 2433.3
  Top Layer w5.9: v1(4641.7,4252) 4700.7,4252 R3.1 4744.1,4208.5 4744.1,4130.2 4748.3,4126 4765.8,4126 4777.3,4137.5 4790.4,4137.5 4795.6,4142.7 4795.6,4220.8 4862.2,4287.4 v1(4925.2,4287.4) ; v1(5212.6,4082.7) 5301,4082.7 U9.11
  Bottom Layer w5.9: CN4.1 3358.7,4094.9 3578.7,4315 4578.7,4315 v1(4641.7,4252) ; v1(4925.2,4287.4) 5129.9,4082.7 v1(5212.6,4082.7)
key1: U6.15
key2: U6.16
M1A: C42.1 D43.1 D44.2 Q14.3 Q15.2 U3.6 U18.6 | length 1518.2
  Top Layer w5.9: C42.1 5688.5,3811.5 5582.7,3917.3 5582.7,3960.6 5594.3,3972.2 U18.6 5720.3,3972.2 5748,4000 6007.1,4000 Q14.3
  Top Layer w39.4: Q14.3 6092,4009.8 Q15.2 6359.7,3902.4 D44.2 ; D43.1 D44.2 ; U3.6 6616.1,3915.4 6603.2,3902.4 D44.2
M1B: C44.1 D45.1 D46.2 Q16.3 Q17.2 U3.1 U19.6 | length 1466.2
  Top Layer w5.9: C44.1 5688.5,3272.1 5606.3,3354.3 5606.3,3421.3 5617.7,3432.6 U19.6 5993.5,3432.6 Q16.3
  Top Layer w39.4: Q16.3 6093.2,3450.1 6274.6,3268.7 Q17.2 6445.1,3258.8 D46.2 D45.1 6626.6,3388.4 U3.1
PWMD1O: U9.13 U18.2 | length 263.1
  Top Layer w5.9: U9.13 v1(5362.2,4128.9) ; v1(5362.2,4011.8) 5388.6,4011.8 5399,4022.2 U18.2
  Bottom Layer w5.9: v1(5362.2,4011.8) v1(5362.2,4128.9)
PWMD2O: U9.15 U19.2 | length 889
  Top Layer w5.9: U9.15 5349.4,4180.1 5354.3,4185 v1(5393.7,4185) ; v1(5370.1,3480.3) 5372.4,3482.6 U19.2
  Bottom Layer w5.9: v1(5370.1,3480.3) 5370.1,3937 5395.7,3962.7 5395.7,4183 v1(5393.7,4185)
RX: U2.1 U6.43 | length 756.1
  Top Layer w5.9: U2.1 5157.3,3051 v1(5220.5,3114.2) ; U6.43 5277.6,3651.6 v1(5291.3,3637.8)
  Bottom Layer w5.9: v1(5220.5,3114.2) 5216.5,3114.2 5208.7,3122 5208.7,3350.4 5315,3456.7 5315,3614.2 v1(5291.3,3637.8)
SDD1O: U9.14 U18.3 | length 335.5
  Top Layer w5.9: U9.14 5310.4,4158.9 v1(5370.1,4158.9) ; v1@5373.8,3976.6 5378,3972.4 5447.4,3972.4 U18.3
  Bottom Layer w5.9: v1(5370.1,4158.9) 5385.8,4143.2 5385.8,3988.2 v1(5374,3976.4)
SDD2O: U9.16 U19.3 | length 974.3
  Top Layer w5.9: U9.16 5306.9,4204.7 5378,4204.7 5385.8,4212.6 v1(5421.3,4212.6) ; v1(5389.8,3433.1) 5451.8,3433.1 U19.3
  Bottom Layer w5.9: v1(5389.8,3433.1) 5421.3,3464.6 v1(5421.3,4212.6)
TX: U2.4 U6.42 | length 705.3
  Top Layer w5.9: v1(5070.9,3200.8) 5136.3,3200.8 U2.4 ; U6.42 5261.8,3631.9 v1(5291.3,3602.4)
  Bottom Layer w5.9: v1(5070.9,3200.8) 5189,3200.8 5192.9,3204.7 5192.9,3350.4 5303.1,3460.6 5303.1,3590.6 v1(5291.3,3602.4)
pads on no net: U1.2 U1.3 U1.5 U6.2 U6.3 U6.4 U6.5 U6.6 U6.8 U6.9 U6.10 U6.11 U6.14 U6.17 U6.18 U6.19 U6.24 U6.25 U6.33 U6.34 U6.35 U6.36 U6.37 U6.38 U6.39 U6.40 U6.41 U6.45 U6.50 U6.51 U6.52 U6.53 U6.54 U6.55 U12.2 U12.3 U12.5
copper on no net:
  other v3: 3129.9,3078.7 6830.7,3078.7 3129.9,4299.2 6830.7,4299.2

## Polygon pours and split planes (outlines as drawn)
GND on Top Layer (solid, remove dead copper, pour order 0): 3011.8,4378 3011.8,3000 6948.8,3000 6948.8,4378
GND on Bottom Layer (solid, remove dead copper, pour order 2): 3011.8,4378 3011.8,3000 6948.8,3000 6948.8,4378

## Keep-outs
Board Outline Layer:
  lines w10: 3023.6,3079.5 3024,3071.7 3025.2,3064 3027.2,3056.4 3029.9,3049.1 3033.3,3042 3037.4,3035.4 3042.1,3029.1 3047.4,3023.4 3053.3,3018.2 3059.6,3013.7 3066.4,3009.8 3073.5,3006.5 3080.9,3004 3088.5,3002.3 3096.3,3001.3 3104.1,3001.1 ; 3023.6,3079.8 3023.6,4300.3 ; 3023.6,4300.7 3024,4308.3 3025.2,4316 3027.1,4323.4 3029.7,4330.7 3033,4337.6 3037,4344.2 3041.6,4350.4 3046.8,4356.1 3052.5,4361.2 3058.7,4365.8 3065.3,4369.8 3072.3,4373.1 3079.6,4375.6 3087,4377.5 3094.7,4378.6 3102.4,4379 6870.3,4374 ; 3102.4,3001.1 6875.8,3001.1 ; 6856.7,4372.9 6864.5,4373.8 6872.3,4374 6880,4373.5 6887.7,4372.2 6895.2,4370.2 6902.5,4367.5 6909.5,4364.1 6916.2,4360 6922.4,4355.4 6928.2,4350.1 6933.5,4344.4 6938.2,4338.2 6942.2,4331.5 6945.7,4324.5 6948.4,4317.2 6950.5,4309.7 6951.8,4302.1 6952.4,4294.3 ; 6876.9,3000.7 6884.5,3001.4 6892,3002.7 6899.3,3004.8 6906.5,3007.6 6913.3,3011.1 6919.7,3015.2 6925.7,3019.9 6931.2,3025.1 6936.2,3030.9 6940.6,3037.1 6944.5,3043.7 6947.6,3050.7 6950.1,3057.9 6951.8,3065.3 6952.8,3072.9 6953.1,3080.5 ; 6952.4,3080.9 6952.4,4291.9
